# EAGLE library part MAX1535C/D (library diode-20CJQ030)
Maxim's MAX1535C/D Highly Integrated Level 2 SMBus Battery Charger General Description: The MAX1535C/D is a highly integrated, multichemistry battery charger that simplifies construction of advanced smart chargers with a minimum number of external components. PIN-PACKAGE: Thin QFN (5mm x 5mm) Features: Compliant with Level 2 Smart Battery Charger Specifications Rev 1.1 Intel SMBus 2-Wire Serial Interface ±0.5% Charge-Voltage Accuracy 11-Bit Charge-Voltage Resolution ±3% Input Current-Limit Accuracy Uses Small (10mOhm) Current-Sense Resistors 8A Maximum Charge Current 6-Bit Input and Charge-Current Resolution 8V to 28V Input Voltage Range 175s Charge Safety Timer Automatic Selection of System Power Source Charges any Battery Chemistry (Li+, NiCd, NiMH, Lead Acid, etc.) Do not use MAX1535A/B due to hardware bugs! It is recommended that you use MAX1535C or MAX1535D! Please send any comments to: messi@users.sourceforge.net
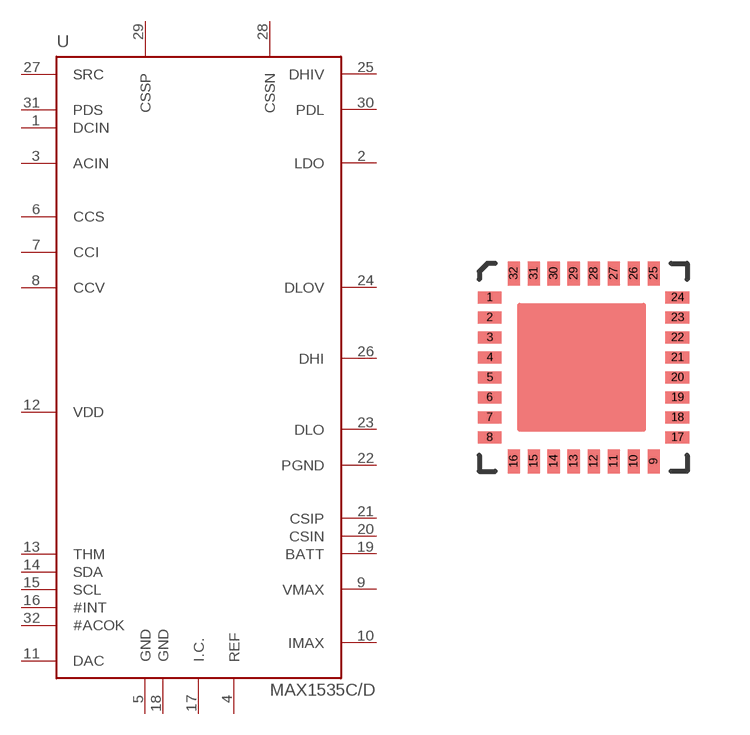
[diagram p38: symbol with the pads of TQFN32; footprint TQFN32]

Designator prefix U

## MAX1535C/D  [TQFN32]
1  DCIN  pwr
2  LDO  out
3  ACIN  pwr
4  REF  pwr
5  GND  pwr
6  CCS  pwr
7  CCI  pwr
8  CCV  pwr
9  VMAX  pwr
10  IMAX  pwr
11  DAC  out
12  VDD  pwr
13  THM  pwr
14  SDA
15  SCL  in
16  #INT  oc
17  I.C.  nc
18  GND  pwr
19  BATT  pwr
20  CSIN  in
21  CSIP  in
22  PGND  pwr
23  DLO  out
24  DLOV  sup
25  DHIV  sup
26  DHI  out
27  SRC  sup
28  CSSN  in
29  CSSP  in
30  PDL  out
31  PDS  out
32  #ACOK  out

## Footprint TQFN32 (pad centres in mm)
Thin QFN32 5x5mm with a 0.5 mm Pitch
smd 0.6 x 0.3: 1 -2.34,1.75; 2 -2.34,1.25; 3 -2.34,0.75; 4 -2.34,0.25; 5 -2.34,-0.25; 6 -2.34,-0.75; 7 -2.34,-1.25; 8 -2.34,-1.75; 17 2.36,-1.75; 18 2.36,-1.25; 19 2.36,-0.75; 20 2.36,-0.25; 21 2.36,0.25; 22 2.36,0.75; 23 2.36,1.25; 24 2.36,1.75
smd 0.3 x 0.6: 9 1.76,-2.35; 10 1.26,-2.35; 11 0.76,-2.35; 12 0.26,-2.35; 13 -0.24,-2.35; 14 -0.74,-2.35; 15 -1.24,-2.35; 16 -1.74,-2.35; 25 1.76,2.35; 26 1.26,2.35; 27 0.76,2.35; 28 0.26,2.35; 29 -0.24,2.35; 30 -0.74,2.35; 31 -1.24,2.35; 32 -1.74,2.35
